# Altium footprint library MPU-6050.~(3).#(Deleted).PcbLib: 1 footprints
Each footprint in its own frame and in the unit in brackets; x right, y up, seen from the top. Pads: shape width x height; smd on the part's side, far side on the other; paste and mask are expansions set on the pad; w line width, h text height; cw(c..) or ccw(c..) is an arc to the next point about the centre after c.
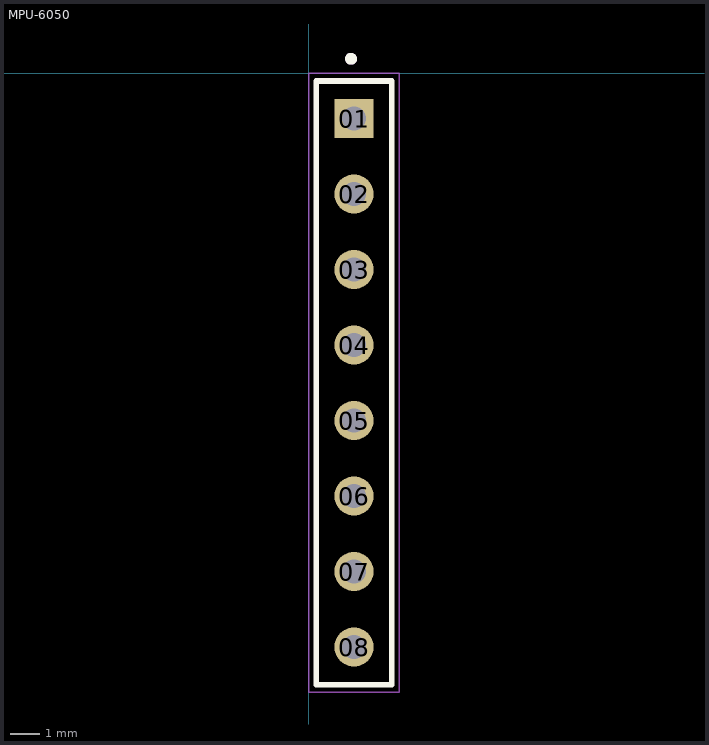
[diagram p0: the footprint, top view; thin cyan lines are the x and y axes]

## MPU-6050 [mil]
pads (8):
  rect 52x52 hole 32: 01(60,-60)
  round 52 hole 32: 02(60,-160) 03(60,-260) 04(60,-360) 05(60,-460) 06(60,-560) 07(60,-660) 08(60,-760)
Top Overlay:
  circle w7.87: c56.06,19.13 r3.94
  lines w7.87: 10,-810 10,-10 110,-10 110,-810 10,-810
Mechanical 13:
  circle w7.87: c56.06,19.13 r3.94
  lines w3.94: 10,-810 110,-810 110,-10 10,-10 10,-810
Mechanical 15:
  lines w1.97: 0.16,-819.84 119.84,-819.84 119.84,-0.16 0.16,-0.16 0.16,-819.84
3D body "MPU6050 With Mounting Hardware.step": height 61.69, standoff -640.43, extent 15,-811.16 615.39,-8.84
